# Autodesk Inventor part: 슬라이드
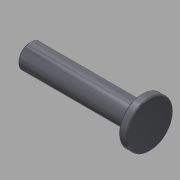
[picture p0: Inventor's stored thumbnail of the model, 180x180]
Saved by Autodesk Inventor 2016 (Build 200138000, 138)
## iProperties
Created: 2015-10
Part Number: 슬라이드
Document SubType Name: Modeling
Designer: mdu
Density: 7.86 g/cm^3
Material: 강철, 연강
Appearance: 강철 - 광택
Mass: 954.83 g
Surface Area: 210.251 cm^2
Volume: 121.48 cm^3
Author: mdu
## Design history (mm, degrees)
sketch "스케치1"
  geometry: L1 (-75, 162)-(-75, 58) reference; L2 (-148, 110)-(2, 110); L3 (-148, 110)-(-148, 125); L4 (-148, 125)-(-8, 125); L5 (-8, 125)-(-8, 139); L6 (-8, 139)-(2, 139); L7 (2, 139)-(2, 110); 2 further points
  constraints: 12 end point, 3 parallel, 3 perpendicular, 1 midpoint, 1 point on line
  dimensions: "d0" = 58 diameter of L6 L2; "d1" = 30 diameter of L4 L2; "d2" = 10 distance of L5.end L6.end; "d3" = 150 distance of L2.start L2.end; "d4" = 73 distance between parallel lines of L3 L1
revolve "회전1" sketch "스케치1" stored, may be unused: angle "d5" = 90 deg
hole "구멍1" diameter "d11" = 13.376; stored, may be unused: countersink angle "d15" = 90 deg, drill point angle "d17" = 118 deg; dims "d9" = 10, "d10" = 10, "d12" = 22, "d13" = 4, "d14" = 2, "d16" = 25
chamfer "모따기1" distance "d6" = 1; stored, may be unused: second distance "d7" = 2, angle "d8" = 45 deg
node "솔리드1"
node "참조1"
